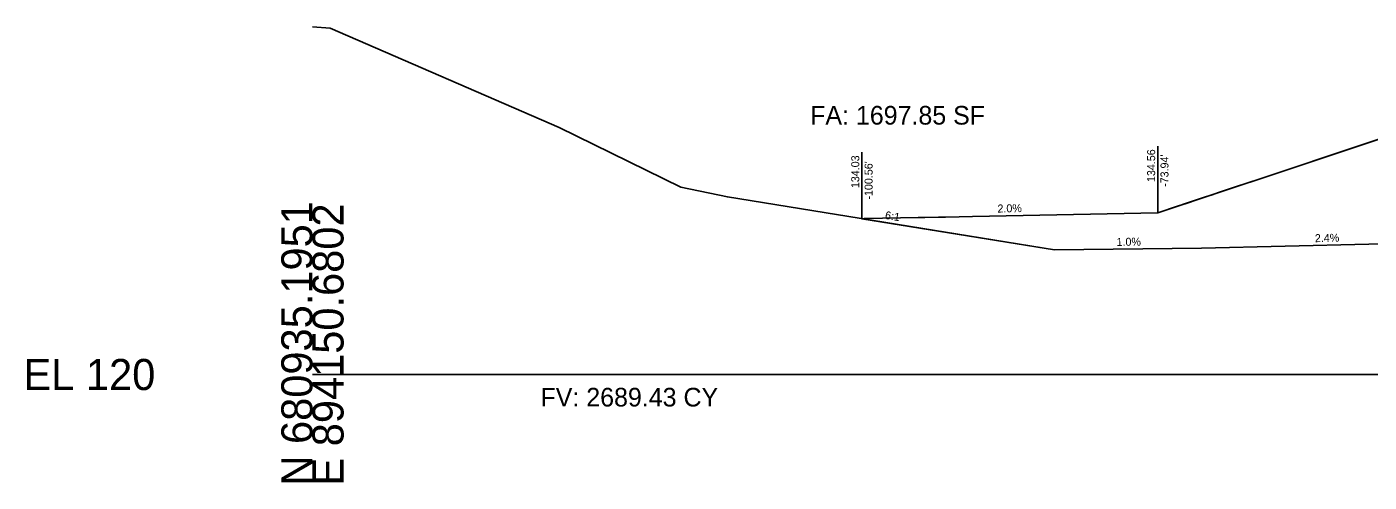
# Model space of a CAD drawing. Extents: x -26 to 4303, y -13 to 10775.
# Drawn here: x 974.3 to 1095.1, y 6990.3 to 7031.3 of the extents above; entities that cross this region are included whole.
import ezdxf

# ---------------------------------------------------------------- set-up
doc = ezdxf.new("R2010")
doc.units = 0
for name, color, linetype in [('CONST_DCH', 7, 'Continuous'), ('Draft_XS_Grid', 7, 'Continuous'), ('DTM_CORRIDOR', 7, 'Continuous'), ('DTM_X_GROUND', 7, 'Continuous'), ('XS_CELL', 7, 'Continuous'), ('XS_M_SHAPES_EARTHWORK', 7, 'Continuous'), ('XS_P_GROUND', 7, 'Continuous'), ('XS_P_TX_CLEARZONE', 7, 'Continuous'), ('XS_P_TX_FS_BS', 7, 'Continuous'), ('XS_SHEET_EW_TX_AREA', 7, 'Continuous'), ('XS_SHEET_EW_TX_VOLUME', 7, 'Continuous')]:
    doc.layers.add(name, color=color, linetype=linetype)

msp = doc.modelspace()

# ---------------------------------------------------------------- linework, layer by layer
at = {"layer": 'DTM_X_GROUND'}
msp.add_lwpolyline([(1000, 7031.3), (1001.6, 7031.18), (1022.19, 7022.25), (1033.15, 7016.88), (1037.34, 7015.99), (1066.76, 7011.23), (1079.98, 7011.36), (1102.58, 7011.9), (1149.99, 7011.05), (1150.07, 7011.05), (1150.15, 7011.05), (1152.17, 7011.01), (1154.68, 7011.4), (1171.88, 7015.14), (1192.06, 7019.57), (1202.28, 7019.56), (1231.74, 7020.01), (1245.67, 7020.28), (1251.65, 7020.24), (1273.34, 7020.08), (1284.06, 7020.35), (1300, 7020.34)], dxfattribs=at)
at = {"layer": 'XS_CELL'}
msp.add_line((1000, 7000), (1150, 7000), dxfattribs=at)
at = {"layer": 'XS_P_GROUND'}
for points in [[(1120.19, 7029.27), (1104.55, 7024.06), (1104.08, 7023.9), (1103.11, 7023.58), (1102.62, 7023.41), (1101.11, 7022.91), (1100.6, 7022.74), (1100.08, 7022.57), (1099.56, 7022.4), (1099.04, 7022.22), (1085, 7017.54), (1084.43, 7017.35), (1082.68, 7016.77), (1081.52, 7016.38), (1080.94, 7016.19), (1080.35, 7015.99), (1076.06, 7014.56)], [(1076.06, 7014.56), (1076.06, 7014.56), (1059.4, 7014.23), (1059.4, 7014.23), (1058.18, 7014.21), (1058.18, 7014.21), (1056.95, 7014.18), (1056.95, 7014.18), (1056.34, 7014.17), (1056.34, 7014.17), (1055.11, 7014.14), (1055.11, 7014.14), (1054.5, 7014.13), (1054.5, 7014.13), (1049.71, 7014.04), (1049.71, 7014.04), (1049.71, 7014.04), (1049.65, 7014.04), (1049.44, 7014.03)]]:
    msp.add_lwpolyline(points, dxfattribs=at)
at = {"layer": 'XS_P_TX_CLEARZONE'}
for p, q in [((1076.06, 7014.56), (1076.06, 7020.56)), ((1076.06, 7014.56), (1076.06, 7020.56)), ((1049.44, 7014.03), (1049.44, 7020.03)), ((1049.44, 7014.03), (1049.44, 7020.03)), ((1049.44, 7014.03), (1049.44, 7020.03))]:
    msp.add_line(p, q, dxfattribs=at)
at = {"layer": 'XS_SHEET_EW_TX_AREA'}
msp.add_lwpolyline([(1105.64, 7024.42), (1084.73, 7017.45), (1083.88, 7017.17), (1081.29, 7016.31), (1079.57, 7015.73), (1078.7, 7015.44), (1077.83, 7015.15), (1076.06, 7014.56), (1059.4, 7014.23), (1058.18, 7014.21), (1056.95, 7014.18), (1056.34, 7014.17), (1055.11, 7014.14), (1054.5, 7014.13), (1049.71, 7014.04), (1049.65, 7014.04), (1049.44, 7014.03), (1066.76, 7011.23), (1079.98, 7011.36), (1102.58, 7011.9)], dxfattribs=at)

# ---------------------------------------------------------------- texts
at = {"layer": 'CONST_DCH'}
msp.add_text('X', height=0.12, dxfattribs=at).set_placement((1076.02, 7014.5))
at = {"layer": 'Draft_XS_Grid'}
msp.add_text('-', height=0.0001, dxfattribs=at).set_placement((1000, 7000))
at = {"layer": 'DTM_CORRIDOR'}
msp.add_text('X', height=0.12, dxfattribs=at).set_placement((1049.4, 7013.97))
at = {"layer": 'XS_CELL'}
for s, p in [('N 680935.1951', (1000, 6990)), ('E 894150.6802', (1002.8, 6990))]:
    msp.add_text(s, height=2.8, rotation=90, dxfattribs=at).set_placement(p)
msp.add_text('EL 120', height=2.8, dxfattribs=at).set_placement((974, 6998.6))
at = {"layer": 'XS_M_SHAPES_EARTHWORK'}
msp.add_text('FV: 2689.43 CY', height=1.68, dxfattribs=at).set_placement((1020.52, 6997.12))
at = {"layer": 'XS_P_TX_CLEARZONE'}
for s, p in [('134.56', (1075.82, 7017.33)), ('134.56', (1075.82, 7017.33)), ('134.03', (1049.2, 7016.78)), ('134.03', (1049.2, 7016.78)), ('134.03', (1049.2, 7016.78)), ("-100.56'", (1050.4, 7015.75)), ("-100.56'", (1050.4, 7015.75)), ("-100.56'", (1050.4, 7015.75)), ("-73.94'", (1077.02, 7016.89)), ("-73.94'", (1077.02, 7016.89))]:
    msp.add_text(s, height=0.72, rotation=90, dxfattribs=at).set_placement(p)
at = {"layer": 'XS_P_TX_FS_BS'}
for s, rotation, p in [('6:1', 350.7979, (1051.48, 7014.01)), ('2.0%', 1.1458, (1061.64, 7014.58)), ('1.0%', 0.5965, (1072.35, 7011.58)), ('2.4%', 1.3714, (1090.2, 7011.91))]:
    msp.add_text(s, height=0.72, rotation=rotation, dxfattribs=at).set_placement(p)
at = {"layer": 'XS_SHEET_EW_TX_VOLUME'}
msp.add_text('FA: 1697.85 SF', height=1.68, dxfattribs=at).set_placement((1044.78, 7022.5))

doc.saveas('drawing.dxf')
